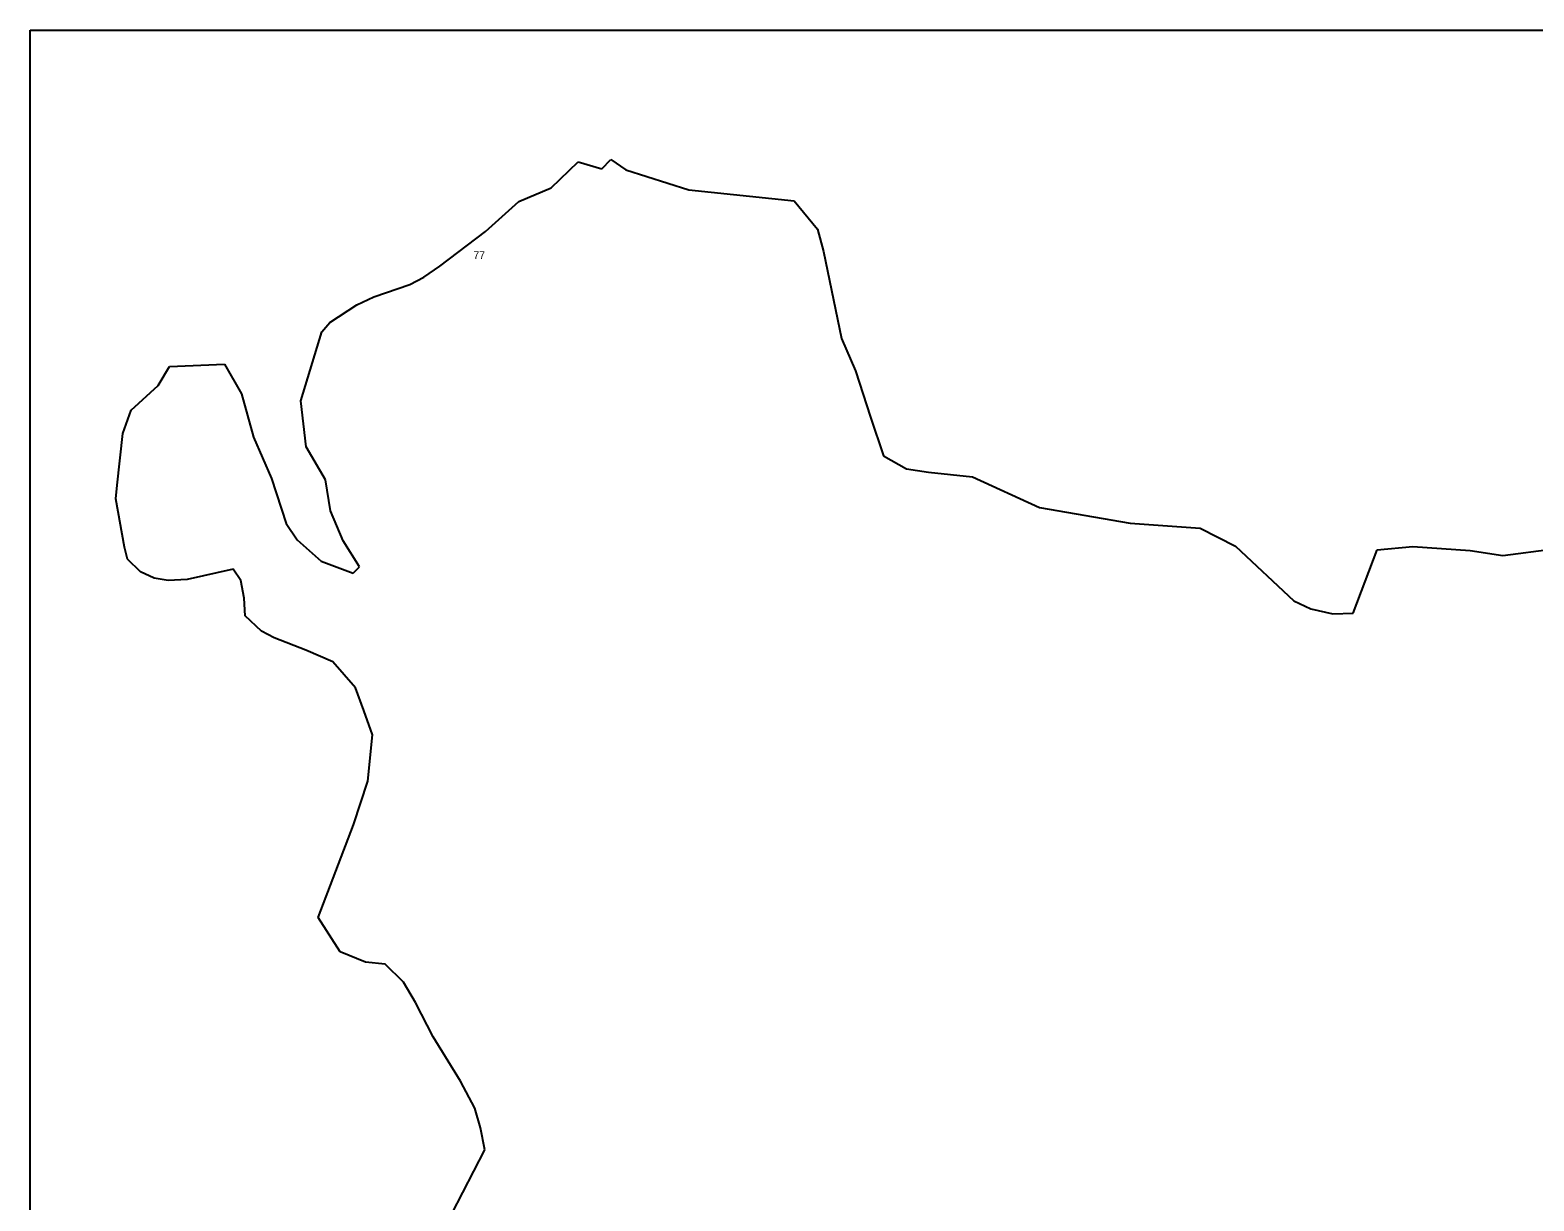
# Model space of a CAD drawing. Extents: x -772884 to -769704, y -986653 to -984166.
# Drawn here: x -772884 to -771287, y -985410 to -984166 of the extents above; entities that cross this region are included whole.
import ezdxf

# ---------------------------------------------------------------- set-up
doc = ezdxf.new("R2010")
doc.units = 0
doc.layers.add('Vrstva 15', color=7, linetype='Continuous')
doc.layers.add('Vrstva 24', color=7, linetype='Continuous')

msp = doc.modelspace()

# ---------------------------------------------------------------- linework, layer by layer
at = {"layer": 'Vrstva 15'}
for p, q in [((-772330.23, -984333.49), (-772301.45, -984306.06)), ((-772301.45, -984306.06), (-772276.28, -984313.25)), ((-772276.28, -984313.25), (-772266.81, -984303.34)), ((-772266.81, -984303.34), (-772251.11, -984314.54)), ((-772251.11, -984314.54), (-772184.02, -984335.69)), ((-772364.44, -984347.99), (-772330.23, -984333.49)), ((-772399.97, -984379.94), (-772364.44, -984347.99)), ((-772184.02, -984335.69), (-772072.3, -984347.29)), ((-772072.3, -984347.29), (-772047.34, -984377.54)), ((-772448.56, -984416.72), (-772399.97, -984379.94)), ((-772047.34, -984377.54), (-772040.88, -984401.33)), ((-772040.88, -984401.33), (-772021.94, -984493.71)), ((-772480.41, -984436.22), (-772465.59, -984428.32)), ((-772465.59, -984428.32), (-772448.56, -984416.72)), ((-772518.58, -984449.29), (-772480.41, -984436.22)), ((-772565.41, -984476.61), (-772536.64, -984457.96)), ((-772536.64, -984457.96), (-772518.58, -984449.29)), ((-772573.63, -984486.6), (-772565.41, -984476.61)), ((-772596.24, -984559.84), (-772573.63, -984486.6)), ((-772021.94, -984493.71), (-772007.12, -984527.9)), ((-772747.47, -984543.53), (-772735.65, -984523.37)), ((-772735.65, -984523.37), (-772677.01, -984520.91)), ((-772677.01, -984520.91), (-772659.09, -984552.34)), ((-772007.12, -984527.9), (-771990.97, -984577.28)), ((-772776.25, -984569.67), (-772747.47, -984543.53)), ((-772659.09, -984552.34), (-772646.18, -984598.45)), ((-772785.05, -984594.63), (-772776.25, -984569.67)), ((-772590.37, -984608.49), (-772596.24, -984559.84)), ((-771990.97, -984577.28), (-771977.16, -984618.25)), ((-772791.22, -984649.34), (-772785.05, -984594.63)), ((-772646.18, -984598.45), (-772627.24, -984642.22)), ((-772569.97, -984643.74), (-772590.37, -984608.49)), ((-771977.16, -984618.25), (-771952.94, -984631.91)), ((-771952.94, -984631.91), (-771929.6, -984635.58)), ((-771929.6, -984635.58), (-771882.7, -984640.39)), ((-772792.47, -984663.84), (-772791.22, -984649.34)), ((-772627.24, -984642.22), (-772611.53, -984689.95)), ((-772564.72, -984676.76), (-772569.97, -984643.74)), ((-771882.7, -984640.39), (-771811.57, -984672.96)), ((-772783.44, -984715.17), (-772792.47, -984663.84)), ((-772550.95, -984708.32), (-772564.72, -984676.76)), ((-771811.57, -984672.96), (-771715.25, -984689.7)), ((-772611.53, -984689.95), (-772600.08, -984707.28)), ((-771715.25, -984689.7), (-771640.97, -984695.14)), ((-771640.97, -984695.14), (-771603.53, -984714.09)), ((-772780.06, -984727.87), (-772783.44, -984715.17)), ((-772600.08, -984707.28), (-772574.6, -984730)), ((-772533.64, -984736.22), (-772550.95, -984708.32)), ((-771603.53, -984714.09), (-771541.58, -984772.25)), ((-771453.13, -984718.09), (-771415.18, -984714.64)), ((-771415.18, -984714.64), (-771354.4, -984718.87)), ((-772766.19, -984741.38), (-772780.06, -984727.87)), ((-772574.6, -984730), (-772540.32, -984742.92)), ((-771478.45, -984785.17), (-771453.13, -984718.09)), ((-771354.4, -984718.87), (-771319.53, -984724.12)), ((-771319.53, -984724.12), (-771265.5, -984717.02)), ((-772751.8, -984748.28), (-772766.19, -984741.38)), ((-772736.83, -984750.78), (-772751.8, -984748.28)), ((-772667.77, -984738.57), (-772716.94, -984749.46)), ((-772659.91, -984750.7), (-772667.77, -984738.57)), ((-772540.32, -984742.92), (-772533.64, -984736.22)), ((-772716.94, -984749.46), (-772736.83, -984750.78)), ((-772656.09, -984769.28), (-772659.91, -984750.7)), ((-772655.07, -984788.3), (-772656.09, -984769.28)), ((-771541.58, -984772.25), (-771523.67, -984780.62)), ((-771523.67, -984780.62), (-771500.18, -984785.91)), ((-772637.97, -984804.46), (-772655.07, -984788.3)), ((-771500.18, -984785.91), (-771478.45, -984785.17)), ((-772624.24, -984811.5), (-772637.97, -984804.46)), ((-772590.68, -984824.77), (-772624.24, -984811.5)), ((-772562.2, -984836.81), (-772590.68, -984824.77)), ((-772537.98, -984864.71), (-772562.2, -984836.81)), ((-772529.03, -984888.8), (-772537.98, -984864.71)), ((-772520.07, -984914.5), (-772529.03, -984888.8)), ((-772524.92, -984963.85), (-772520.07, -984914.5)), ((-772540.04, -985009.96), (-772524.92, -984963.85)), ((-772577.62, -985108.65), (-772540.04, -985009.96)), ((-772554.36, -985145.04), (-772577.62, -985108.65)), ((-772527.5, -985155.91), (-772554.36, -985145.04)), ((-772506.5, -985157.97), (-772527.5, -985155.91)), ((-772487.2, -985177.25), (-772506.5, -985157.97)), ((-772474.28, -985198.69), (-772487.2, -985177.25)), ((-772455.49, -985235.26), (-772474.28, -985198.69)), ((-772426.57, -985282.4), (-772455.49, -985235.26)), ((-772411.45, -985311.04), (-772426.57, -985282.4)), ((-772405.29, -985332.04), (-772411.45, -985311.04)), ((-772400.73, -985355.31), (-772405.29, -985332.04)), ((-772456.23, -985463.11), (-772400.73, -985355.31))]:
    msp.add_line(p, q, dxfattribs=at)
msp.add_lwpolyline([(-772883.58, -984166.02), (-769704.46, -984166.02), (-769704.46, -986653.05), (-772883.58, -986653.05)], close=True, dxfattribs=at)

# ---------------------------------------------------------------- texts
at = {"layer": 'Vrstva 24'}
msp.add_text('77', height=8.2944, dxfattribs=at).set_placement((-772412.817, -984409.185))

doc.saveas('drawing.dxf')
